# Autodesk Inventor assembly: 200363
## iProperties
Created: 2007-12
Part Number: 200363
Document SubType Name: Assembly
Designer: MM
Mass: 2378.9 g
Surface Area: 2756.58 cm^2
Volume: 333.729 cm^3
Density: 7.12825 g/cm^3
Description: BOTTOM RAIL ASSEMBLY
Component Category: Lower Component
Author: MM
